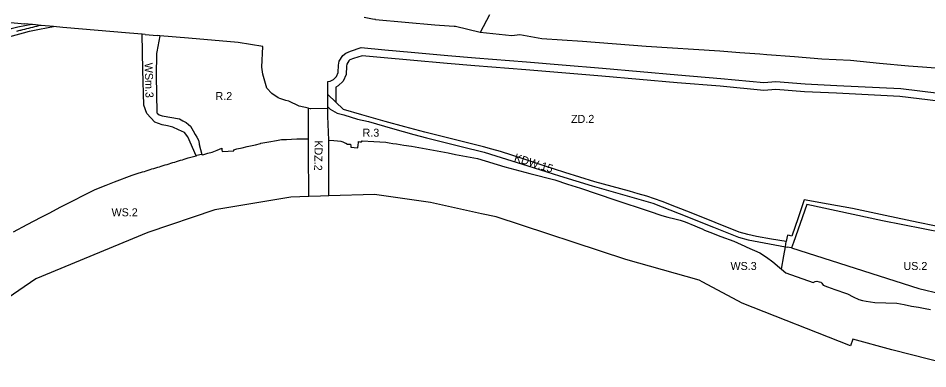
# Model space of a CAD drawing. Extents: x 7431080 to 7433370, y 5546450 to 5548428.
# Drawn here: x 7431653 to 7432562, y 5546469 to 5546820 of the extents above; entities that cross this region are included whole.
import ezdxf

# ---------------------------------------------------------------- set-up
doc = ezdxf.new("R2010")
doc.units = 0
for name, color, linetype in [('Linie Rozgraniczajace', 7, 'Continuous'), ('nieprzekraczalna linia zabudowy', 7, 'Continuous'), ('oznaczenia_przeznaczen', 7, 'Continuous')]:
    doc.layers.add(name, color=color, linetype=linetype)

msp = doc.modelspace()

# ---------------------------------------------------------------- linework, layer by layer
at = {"layer": 'Linie Rozgraniczajace'}
for p, q in [((7432124.29, 5546823.16), (7432114.87, 5546805.62)), ((7431920.52, 5546737.66), (7431914.68, 5546739.66)), ((7431962.51, 5546743.57), (7431978.16, 5546728.66)), ((7431978.5, 5546723.18), (7431992.25, 5546718.97)), ((7431992.25, 5546718.97), (7432003.05, 5546716.56)), ((7431837.04, 5546683.2), (7431834.13, 5546693.34)), ((7431963.41, 5546697.92), (7431968.6, 5546697.59)), ((7431963.45, 5546642.14), (7431963.43, 5546697.6)), ((7431968.6, 5546697.59), (7431972.06, 5546697.22)), ((7431972.06, 5546697.22), (7431975.52, 5546696.85)), ((7431975.52, 5546696.85), (7431977.56, 5546696.06)), ((7431977.56, 5546696.06), (7431979.61, 5546695.28)), ((7431979.61, 5546695.28), (7431980.63, 5546694.8)), ((7431980.63, 5546694.8), (7431982.25, 5546694.03)), ((7431982.25, 5546694.03), (7431983.52, 5546693.94)), ((7431983.52, 5546693.94), (7431984.49, 5546693.87)), ((7431984.49, 5546693.87), (7431985, 5546693.83)), ((7431985, 5546693.83), (7431985.35, 5546693.8)), ((7431985.35, 5546693.8), (7431985.47, 5546692.02)), ((7431985.47, 5546692.02), (7431985.55, 5546690.7)), ((7431985.55, 5546690.7), (7431989.01, 5546690.5)), ((7431992.47, 5546690.31), (7431992.87, 5546693.1)), ((7431992.87, 5546693.1), (7431993.18, 5546695.22)), ((7431993.18, 5546695.22), (7431993.35, 5546696.38)), ((7431993.35, 5546696.38), (7431994.45, 5546696.34)), ((7431994.45, 5546696.34), (7431995.8, 5546696.3)), ((7431995.8, 5546696.3), (7431996.25, 5546696.28)), ((7431996.25, 5546696.28), (7431996.72, 5546697.05)), ((7431996.72, 5546697.05), (7432008.63, 5546696.4)), ((7432008.63, 5546696.4), (7432020.54, 5546695.75)), ((7432020.54, 5546695.75), (7432023.81, 5546695.21)), ((7432023.81, 5546695.21), (7432027.52, 5546694.64)), ((7432027.52, 5546694.64), (7432031.22, 5546694.07)), ((7432031.22, 5546694.07), (7432038.64, 5546692.94)), ((7432038.64, 5546692.94), (7432046.05, 5546691.8)), ((7432046.05, 5546691.8), (7432057.12, 5546689.85)), ((7431989.01, 5546690.5), (7431992.47, 5546690.31)), ((7432057.12, 5546689.85), (7432060.81, 5546689.16)), ((7432060.81, 5546689.16), (7432068.19, 5546687.79)), ((7432068.19, 5546687.79), (7432075.56, 5546686.41)), ((7432075.56, 5546686.41), (7432082.93, 5546685.03)), ((7432082.93, 5546685.03), (7432090.3, 5546683.65)), ((7432090.3, 5546683.65), (7432101.29, 5546681.59)), ((7432101.29, 5546681.59), (7432112.29, 5546679.53)), ((7432112.29, 5546679.53), (7432139.47, 5546671.08)), ((7432139.47, 5546671.08), (7432164.42, 5546664.58)), ((7432164.42, 5546664.58), (7432189.37, 5546658.09)), ((7432189.37, 5546658.09), (7432202.24, 5546653.9)), ((7432202.24, 5546653.9), (7432215.11, 5546649.71)), ((7432215.11, 5546649.71), (7432249.46, 5546638.27)), ((7432249.46, 5546638.27), (7432283.82, 5546626.83)), ((7432283.82, 5546626.83), (7432296.57, 5546622.41)), ((7432296.57, 5546622.41), (7432302.53, 5546620.97)), ((7432302.53, 5546620.97), (7432309.38, 5546619.32)), ((7432309.38, 5546619.32), (7432314.61, 5546617.7)), ((7432314.61, 5546617.7), (7432319.6, 5546616.17)), ((7432319.6, 5546616.17), (7432329.39, 5546612.04)), ((7432329.39, 5546612.04), (7432333.99, 5546610.1)), ((7432333.99, 5546610.1), (7432336.61, 5546609)), ((7432336.61, 5546609), (7432339.22, 5546607.9)), ((7432339.22, 5546607.9), (7432341.83, 5546606.79)), ((7432341.83, 5546606.79), (7432344.37, 5546605.8)), ((7432344.37, 5546605.8), (7432355.53, 5546601.6)), ((7432355.53, 5546601.6), (7432368.4, 5546596.75)), ((7432368.4, 5546596.75), (7432379.33, 5546591.89)), ((7432379.33, 5546591.89), (7432381.46, 5546590.95)), ((7432381.46, 5546590.95), (7432394.52, 5546585.14)), ((7432419.92, 5546591.22), (7432421.86, 5546590.85)), ((7432394.52, 5546585.14), (7432401, 5546580.66)), ((7432401, 5546580.66), (7432407.47, 5546576.18)), ((7432407.47, 5546576.18), (7432413.99, 5546570.57)), ((7432413.99, 5546570.57), (7432416.06, 5546568.78)), ((7432416.06, 5546568.78), (7432420.5, 5546564.96)), ((7432420.5, 5546564.96), (7432447.68, 5546555.57)), ((7432447.68, 5546555.57), (7432449.78, 5546556.34)), ((7432449.78, 5546556.34), (7432451.19, 5546556.87)), ((7432451.19, 5546556.87), (7432453.66, 5546556.24)), ((7432453.66, 5546556.24), (7432455.4, 5546555.67)), ((7432455.4, 5546555.67), (7432456.22, 5546554.65)), ((7432456.22, 5546554.65), (7432457.73, 5546552.77)), ((7432457.73, 5546552.77), (7432461.93, 5546551.28)), ((7432461.93, 5546551.28), (7432465.69, 5546549.93)), ((7432465.69, 5546549.93), (7432469.46, 5546548.59)), ((7432469.46, 5546548.59), (7432473.23, 5546547.25)), ((7432473.23, 5546547.25), (7432477, 5546545.91)), ((7432477, 5546545.91), (7432482.04, 5546544.11)), ((7432482.04, 5546544.11), (7432487.67, 5546541.2)), ((7432487.67, 5546541.2), (7432493.3, 5546538.29)), ((7432493.3, 5546538.29), (7432497.04, 5546537.56)), ((7432497.04, 5546537.56), (7432500.78, 5546536.83)), ((7432500.78, 5546536.83), (7432505.07, 5546536.12)), ((7432505.07, 5546536.12), (7432509.35, 5546535.41)), ((7432509.35, 5546535.41), (7432520.39, 5546535.01)), ((7432520.39, 5546535.01), (7432531.43, 5546534.62)), ((7432531.43, 5546534.62), (7432538.71, 5546533.28)), ((7432538.71, 5546533.28), (7432545.98, 5546531.93)), ((7432545.98, 5546531.93), (7432552.88, 5546530.72)), ((7432552.88, 5546530.72), (7432559.77, 5546529.51)), ((7432559.77, 5546529.51), (7432564.97, 5546528.5))]:
    msp.add_line(p, q, dxfattribs=at)
for points in [[(7432595.27, 5546768.02), (7432557.05, 5546770.94), (7432543.08, 5546772), (7432514, 5546774.74), (7432484.92, 5546777.47), (7432470.7, 5546778.25), (7432456.47, 5546779.03), (7432428.92, 5546781.09), (7432401.38, 5546783.15), (7432394.41, 5546783.81), (7432374.4, 5546785.29), (7432354.39, 5546786.78), (7432280.61, 5546791.73), (7432217.05, 5546796.45), (7432196.82, 5546797.83), (7432176.58, 5546799.21), (7432154.39, 5546803.12), (7432146.54, 5546802.3), (7432114.87, 5546805.62), (7432090.15, 5546811.52), (7432088.83, 5546811.61), (7432083.72, 5546811.92), (7432069.38, 5546812.82), (7432039.73, 5546815.52), (7432010.07, 5546818.22), (7432010.33, 5546818.74), (7432007.05, 5546819.09), (7431998.82, 5546820.5)], [(7431666.52, 5546813.54), (7431652.76, 5546810.83), (7431646.05, 5546809.19), (7431632.69, 5546805.73), (7431614.04, 5546798.55), (7431573.8, 5546782.64), (7431564.7, 5546778.48), (7431551.36, 5546772.34), (7431547.12, 5546770.36), (7431530.22, 5546761.49), (7431474.45, 5546734.76), (7431439.19, 5546725.31), (7431425.46, 5546723.7), (7431410.61, 5546722.15), (7431395.76, 5546720.59), (7431388.63, 5546718.7)], [(7431456.45, 5546718.75), (7431471.59, 5546726.27), (7431509.4, 5546744.32), (7431547.2, 5546762.37), (7431571.9, 5546774.39), (7431588.96, 5546781.5), (7431610.07, 5546790.44), (7431627, 5546796.1), (7431643.53, 5546801.34), (7431658.3, 5546805.17), (7431664.35, 5546806.81), (7431674.43, 5546808.97), (7431688.31, 5546811.48)], [(7431613.63, 5546817.91), (7431620.23, 5546817.42), (7431621.77, 5546817.3), (7431628, 5546816.84), (7431640.51, 5546815.97), (7431644.37, 5546815.71), (7431648.98, 5546815.38), (7431659.79, 5546814.25)], [(7431675.93, 5546812.65), (7431673.8, 5546812.28), (7431673.43, 5546812.19), (7431671.42, 5546811.7), (7431669.42, 5546811.2), (7431667.41, 5546810.71), (7431665.4, 5546810.22), (7431663.4, 5546809.72), (7431661.39, 5546809.23), (7431659.39, 5546808.74), (7431657.38, 5546808.24), (7431655.38, 5546807.75), (7431654.49, 5546807.53), (7431653.39, 5546807.2), (7431651.41, 5546806.6)], [(7431779.91, 5546803.64), (7431776.8, 5546803.91), (7431764.19, 5546805.03), (7431697.63, 5546810.6), (7431688.31, 5546811.48), (7431675.93, 5546812.65), (7431667.19, 5546813.47), (7431666.52, 5546813.54), (7431659.79, 5546814.25)], [(7431830.82, 5546682.26), (7431822.71, 5546701.17), (7431819.33, 5546705.58), (7431813.42, 5546708.26), (7431807.52, 5546710.94), (7431802.27, 5546712.11), (7431797.01, 5546713.27), (7431789.59, 5546715.96), (7431781.6, 5546724.67), (7431778.53, 5546732.82), (7431777.67, 5546768.17), (7431776.8, 5546803.91)], [(7431779.91, 5546803.64), (7431792.01, 5546802.57)], [(7431794.52, 5546802.35), (7431791.75, 5546786.27), (7431791.36, 5546784.5), (7431790.91, 5546762.09), (7431791.64, 5546725.58)], [(7431914.68, 5546739.66), (7431912.83, 5546740.37), (7431906.7, 5546744.62), (7431901.59, 5546749.97), (7431897.58, 5546764.05), (7431896.64, 5546770.75), (7431897.52, 5546791.44), (7431873, 5546795.48), (7431823.31, 5546799.82), (7431794.52, 5546802.35), (7431792.01, 5546802.57)], [(7431962.53, 5546756.43), (7431964.77, 5546756.91), (7431968.17, 5546758.69), (7431971.13, 5546761.57), (7431972.93, 5546765.43), (7431973.12, 5546772.88), (7431973.97, 5546776.98), (7431977.58, 5546782.6), (7431980.48, 5546785.02), (7431985.25, 5546786.97), (7431995.75, 5546790.51), (7432019.58, 5546788.34), (7432045.69, 5546785.96), (7432082.5, 5546782.64), (7432110.03, 5546780.23), (7432161.2, 5546776.11), (7432196.93, 5546773.17), (7432236.99, 5546769.99), (7432312.44, 5546763.31), (7432355.47, 5546759.7), (7432398.27, 5546755.46), (7432410.29, 5546756.47), (7432439.63, 5546754.33), (7432471.43, 5546752.73), (7432535.17, 5546749.53), (7432573.37, 5546744.73)], [(7431963.43, 5546697.6), (7431963.41, 5546697.92), (7431962.48, 5546721.9), (7431962.5, 5546729.87), (7431962.49, 5546731.06), (7431962.49, 5546731.33), (7431962.5, 5546737.35), (7431962.51, 5546743.57), (7431962.53, 5546756.43)], [(7431943.34, 5546729.85), (7431933.97, 5546731.76), (7431923.57, 5546736.83), (7431920.52, 5546737.66)], [(7431943.34, 5546729.85), (7431944.78, 5546729.55), (7431945.66, 5546729.57), (7431962.5, 5546729.87)], [(7431943.34, 5546726.42), (7431943.34, 5546729.85)], [(7431962.49, 5546731.06), (7431964.9, 5546728.91), (7431972.03, 5546724.92), (7431978.5, 5546723.18)], [(7432420.83, 5546596.48), (7432406, 5546598.94), (7432391.18, 5546601.4), (7432382.45, 5546603.58), (7432373.71, 5546605.77), (7432349.69, 5546615.4), (7432325.66, 5546625.03), (7432311.12, 5546630.76), (7432296.58, 5546636.5), (7432288.94, 5546639.12), (7432281.29, 5546641.74), (7432272.63, 5546644.24), (7432263.98, 5546646.74), (7432246.63, 5546651.5), (7432229.29, 5546656.25), (7432214.39, 5546660.88), (7432199.49, 5546665.51), (7432178.67, 5546672.35), (7432157.86, 5546679.19), (7432146.45, 5546682.81), (7432135.03, 5546686.43), (7432126.63, 5546688.87), (7432118.23, 5546691.3), (7432088.88, 5546698.62), (7432059.52, 5546705.95), (7432039.62, 5546711.22), (7432019.73, 5546716.49), (7431996.42, 5546723.32), (7431978.16, 5546728.66)], [(7431791.64, 5546725.58), (7431792.05, 5546724.98), (7431793.97, 5546723.27), (7431796.83, 5546722.34), (7431814.38, 5546719.05), (7431817.71, 5546717.33), (7431821.03, 5546715.6), (7431823.12, 5546713.69), (7431825.22, 5546711.78), (7431828.05, 5546707.08), (7431829.97, 5546703.57), (7431831.65, 5546700.76), (7431833.33, 5546697.96), (7431833.6, 5546696.31), (7431833.87, 5546694.67), (7431834, 5546694), (7431834.13, 5546693.34)], [(7431943.3, 5546702.73), (7431943.33, 5546720.32)], [(7431943.33, 5546720.32), (7431943.34, 5546726.42)], [(7432003.05, 5546716.56), (7432027.31, 5546709.55), (7432048.67, 5546703.4), (7432061.32, 5546700.31), (7432095.76, 5546691.61), (7432118.83, 5546685.86), (7432130.49, 5546682.19), (7432162.62, 5546672.14), (7432194.26, 5546662.27), (7432226.71, 5546652.11), (7432259.52, 5546642.68), (7432287.25, 5546634.84), (7432313.69, 5546624.35), (7432348.01, 5546610.76), (7432372.9, 5546600.85), (7432382.6, 5546598.23), (7432419.92, 5546591.22)], [(7431943.47, 5546641.49), (7431943.27, 5546686.87), (7431943.29, 5546697.81), (7431943.29, 5546699.23), (7431943.3, 5546702.73)], [(7431648.3, 5546606.21), (7431662.07, 5546613.48), (7431675.83, 5546620.74), (7431683.89, 5546624.91), (7431695.76, 5546631.04), (7431706.4, 5546636.55), (7431720.79, 5546643.75), (7431730.07, 5546648.4), (7431740.9, 5546652.72), (7431749.31, 5546656.07), (7431766.85, 5546662.91), (7431773.91, 5546665.05), (7431775.39, 5546665.51), (7431777.29, 5546666.09), (7431779.18, 5546666.68), (7431781.08, 5546667.26), (7431782.98, 5546667.85), (7431784.88, 5546668.43), (7431786.77, 5546669.02), (7431788.67, 5546669.6), (7431790.57, 5546670.19), (7431792.47, 5546670.77), (7431794.17, 5546671.3), (7431796.07, 5546671.88), (7431797.97, 5546672.47), (7431799.87, 5546673.05), (7431801.77, 5546673.64), (7431803.81, 5546674.27), (7431805.71, 5546674.85), (7431807.6, 5546675.44), (7431809.5, 5546676.02), (7431811.4, 5546676.61), (7431813.3, 5546677.19), (7431815.2, 5546677.77), (7431817.11, 5546678.32), (7431818.88, 5546678.83), (7431823.08, 5546680.04), (7431830.82, 5546682.26), (7431831.49, 5546682.45), (7431831.68, 5546682.82), (7431836.14, 5546683.99), (7431837.04, 5546683.2), (7431838.49, 5546683.59), (7431840.58, 5546684.16), (7431842.66, 5546684.72), (7431846.85, 5546685.85), (7431851.75, 5546687.81), (7431856.64, 5546689.77), (7431856.74, 5546688.07), (7431856.84, 5546686.37), (7431862.75, 5546686.73), (7431868.65, 5546687.09), (7431868.5, 5546688.36), (7431871.46, 5546689.04), (7431876.83, 5546690.27), (7431881.8, 5546691.41), (7431890.27, 5546693.35), (7431895.11, 5546694.46), (7431895.57, 5546694.82), (7431903.47, 5546696.18), (7431911.36, 5546697.54), (7431916.28, 5546698.39), (7431921.19, 5546698.68), (7431926.29, 5546698.99), (7431931.39, 5546699.3), (7431937.22, 5546699.28), (7431943.05, 5546699.25), (7431943.29, 5546699.23)], [(7432601.02, 5546469.08), (7432526.29, 5546488.21), (7432487.19, 5546498.64), (7432485.15, 5546492.1), (7432376.88, 5546534.94), (7432337.43, 5546555.86), (7432333.87, 5546557.74), (7432260.46, 5546578.5), (7432130.65, 5546621.08), (7432116.01, 5546624.29), (7432065.32, 5546635.38), (7432009.15, 5546643.61), (7431963.45, 5546642.14), (7431955.18, 5546641.87), (7431943.47, 5546641.49), (7431925.66, 5546640.92), (7431849.45, 5546628.25), (7431782.51, 5546605.39), (7431670.62, 5546559.16), (7431579.86, 5546497.22)], [(7432438.77, 5546638.33), (7432432.61, 5546620.11), (7432426.45, 5546601.88), (7432424.17, 5546602.39), (7432421.89, 5546602.9), (7432421.36, 5546599.69), (7432420.83, 5546596.48)], [(7432653.11, 5546573.41), (7432643.73, 5546585.86), (7432634.34, 5546598.3), (7432626.24, 5546600.26), (7432618.13, 5546602.23), (7432585.37, 5546608.83), (7432552.61, 5546615.42), (7432519.74, 5546622.4), (7432486.87, 5546629.37), (7432462.82, 5546633.85), (7432438.77, 5546638.33)], [(7432650.42, 5546568.68), (7432631.42, 5546593.86), (7432618.5, 5546597), (7432516.99, 5546617.06), (7432441.27, 5546633.46), (7432427.92, 5546595.44)], [(7432416.06, 5546568.78), (7432418.38, 5546582.23), (7432419.92, 5546591.22)], [(7432419.92, 5546591.22), (7432420.83, 5546596.48)], [(7432427.92, 5546595.44), (7432426.16, 5546590.03), (7432421.86, 5546590.85)]]:
    msp.add_lwpolyline(points, dxfattribs=at)
at = {"layer": 'nieprzekraczalna linia zabudowy'}
for points in [[(7432572.81, 5546736.74), (7432534.47, 5546741.56), (7432471.03, 5546744.74), (7432439.14, 5546746.34), (7432410.33, 5546748.45), (7432398.21, 5546747.43), (7432354.74, 5546751.73), (7432311.75, 5546755.34), (7432236.32, 5546762.02), (7432196.29, 5546765.2), (7432160.55, 5546768.14), (7432109.36, 5546772.26), (7432081.79, 5546774.67), (7432044.97, 5546777.99), (7432018.85, 5546780.37), (7431996.71, 5546782.39), (7431988.04, 5546779.47), (7431984.65, 5546778.08), (7431983.65, 5546777.24), (7431981.5, 5546773.9), (7431981.1, 5546771.96), (7431980.88, 5546763.56), (7431977.76, 5546756.86), (7431972.91, 5546752.14), (7431970.52, 5546750.89), (7431970.5, 5546735.96)], [(7432426.16, 5546590.03), (7432553.23, 5546549.34), (7432575.57, 5546544.1), (7432630.17, 5546533.94), (7432734.09, 5546522)]]:
    msp.add_lwpolyline(points, dxfattribs=at)

# ---------------------------------------------------------------- texts
at = {"layer": 'oznaczenia_przeznaczen'}
for s, rotation, p in [('WSm.3', 271.60113, (7431779.35, 5546775.15)), ('WSm.3', 271.60113, (7431779.35, 5546775.15)), ('KDZ.2', 268.83752, (7431949.44, 5546697.74)), ('KDW.15', 342.4671, (7432148.19, 5546677.11))]:
    msp.add_text(s, height=8, rotation=rotation, dxfattribs=at).set_placement(p)
for s, p in [('R.2', (7431850.3, 5546737.99)), ('R.2', (7431850.3, 5546737.99)), ('R.2', (7431850.3, 5546737.99)), ('ZD.2', (7432205.66, 5546715.13)), ('ZD.2', (7432205.66, 5546715.13)), ('ZD.2', (7432205.66, 5546715.13)), ('R.3', (7431997.3, 5546701.34)), ('R.3', (7431997.3, 5546701.34)), ('R.3', (7431997.3, 5546701.34)), ('WS.2', (7431746.34, 5546621.68)), ('WS.3', (7432365.07, 5546567.99)), ('WS.3', (7432365.07, 5546567.99)), ('WS.3', (7432365.07, 5546567.99)), ('US.2', (7432538, 5546567.97)), ('US.2', (7432538, 5546567.97)), ('US.2', (7432538, 5546567.97))]:
    msp.add_text(s, height=8, dxfattribs=at).set_placement(p)

doc.saveas('drawing.dxf')
